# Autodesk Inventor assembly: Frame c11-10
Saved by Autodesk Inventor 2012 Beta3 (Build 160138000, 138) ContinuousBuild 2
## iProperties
Created: 2011-01
Part Number: Frame c11-10
Document SubType Name: Assembly
Designer: Beta-8540w
_FrameDoc: Frame Assembly
_Version: 15.0.0
Author: Beta-8540w
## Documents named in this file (20)
- C:\Inventor 2012 Essentials\Assemblies\Chapter 11\Frame\Frame c11-10.iam
- C:\Inventor 2012 Essentials\Assemblies\Chapter 11\Frame\Skeleton-c11-10.ipt
- C:\Inventor 2012 Essentials\Assemblies\Chapter 11\Frame\ANSI L 1.5 x 1.5 x 3_16 00000005.ipt
- ANSI L 1.5 x 1.5 x 3_16 00000005.ipt
- C:\Inventor 2012 Essentials\Assemblies\Chapter 11\Frame\ANSI L 1.5 x 1.5 x 3_16 00000006.ipt
- ANSI L 1.5 x 1.5 x 3_16 00000006.ipt
- C:\Inventor 2012 Essentials\Assemblies\Chapter 11\Frame\ANSI 2 1_4x5_16 00000007.ipt
- ANSI 2 1_4x5_16 00000007.ipt
- C:\Inventor 2012 Essentials\Assemblies\Chapter 11\Frame\ANSI 3x3x3_16 00000049.ipt
- ANSI 3x3x3_16 00000049.ipt
- C:\Inventor 2012 Essentials\Assemblies\Chapter 11\Frame\ANSI 3x3x3_16 00000050.ipt
- ANSI 3x3x3_16 00000050.ipt
- C:\Inventor 2012 Essentials\Assemblies\Chapter 11\Frame\ANSI 3x3x3_16 00000051.ipt
- ANSI 3x3x3_16 00000051.ipt
- C:\Inventor 2012 Essentials\Assemblies\Chapter 11\Frame\ANSI 3x3x3_16 00000052.ipt
- ANSI 3x3x3_16 00000052.ipt
- C:\Inventor 2012 Essentials\Assemblies\Chapter 11\Frame\ANSI 3x3x3_16 00000054.ipt
- ANSI 3x3x3_16 00000054.ipt
- C:\Inventor 2012 Essentials\Assemblies\Chapter 11\Frame\ANSI 5x3x3_16 00000055.ipt
- ANSI 5x3x3_16 00000055.ipt
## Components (10 placed, 10 different names)
1. Frame Reference Model
2. ANSI L 1.5 x 1.5 x 3_16 00000005:1
3. ANSI L 1.5 x 1.5 x 3_16 00000006:1
4. ANSI 2 1_4x5_16 00000007:1
5. ANSI 3x3x3_16 00000049:1
6. ANSI 3x3x3_16 00000050:1
7. ANSI 3x3x3_16 00000051:1
8. ANSI 3x3x3_16 00000052:1
9. ANSI 3x3x3_16 00000054:1
10. ANSI 5x3x3_16 00000055:1
